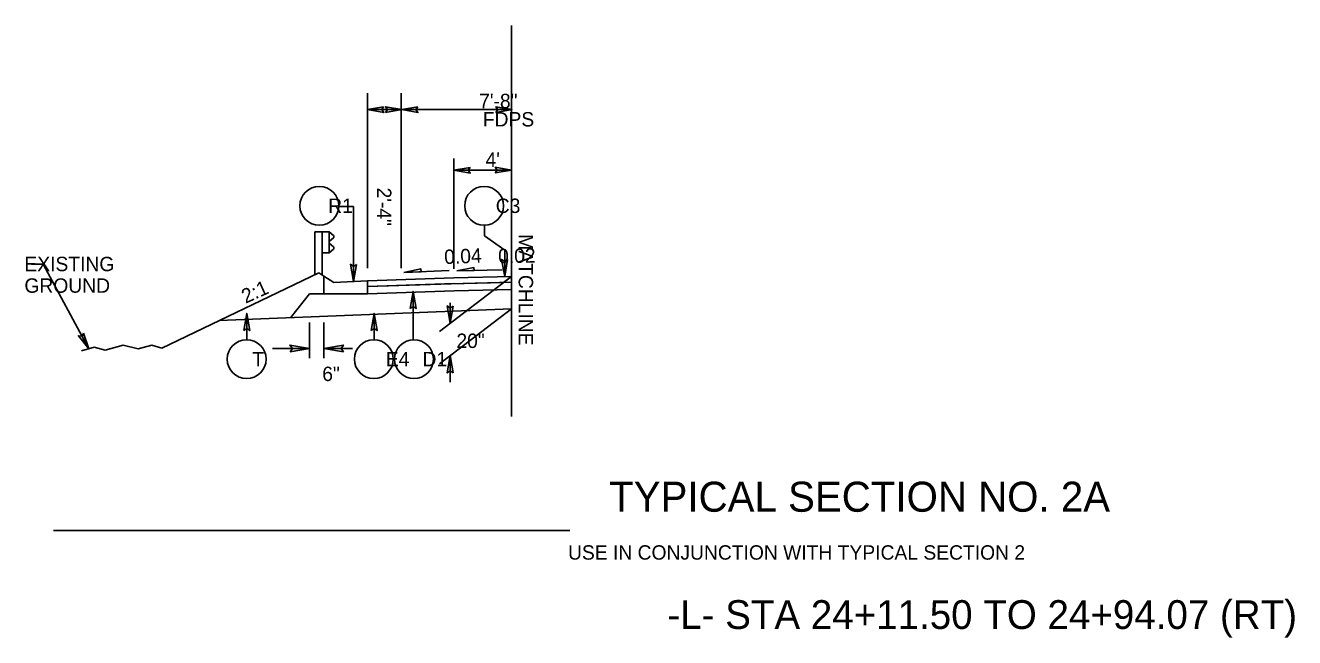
# Model space of a CAD drawing. Extents: x 574442 to 2463611, y -53527 to 675895.
# Drawn here: x 2463523.4 to 2463611.5, y 675852 to 675894.6 of the extents above; entities that cross this region are included whole.
import ezdxf

# ---------------------------------------------------------------- set-up
doc = ezdxf.new("R2010")
doc.units = 0
for name, color, linetype in [('Old_Level_1', 7, 'Continuous'), ('Old_Level_22', 7, 'Continuous'), ('Old_Level_23', 7, 'Continuous'), ('Old_Level_3', 7, 'Continuous'), ('Prop Shade Heavy', 7, 'Continuous'), ('Typical Curb CELL', 7, 'Continuous'), ('Typical Guardrail CELL', 7, 'Continuous')]:
    doc.layers.add(name, color=color, linetype=linetype)

msp = doc.modelspace()

# ---------------------------------------------------------------- linework, layer by layer
at = {"layer": 'Old_Level_1'}
msp.add_line((2463557.126, 675887.114), (2463557.126, 675887.114), dxfattribs=at)
at = {"layer": 'Old_Level_22'}
for p, q in [((2463543.749, 675877.391), (2463532.851, 675872.157)), ((2463544.106, 675877.148), (2463543.749, 675877.391)), ((2463553.126, 675877.03), (2463547.126, 675876.822)), ((2463557.126, 675877.134), (2463553.126, 675877.03)), ((2463553.14, 675876.63), (2463547.126, 675876.424)), ((2463553.157, 675876.131), (2463547.126, 675875.919)), ((2463557.126, 675876.732), (2463552.939, 675876.622)), ((2463557.126, 675876.231), (2463553.157, 675876.131)), ((2463543.106, 675875.919), (2463541.783, 675874.266)), ((2463543.106, 675875.919), (2463544.106, 675875.919)), ((2463557.126, 675874.879), (2463536.829, 675874.067))]:
    msp.add_line(p, q, dxfattribs=at)
msp.add_lwpolyline([(2463532.851, 675872.157), (2463532.152, 675872.348), (2463531.199, 675872.109), (2463530.165, 675872.348), (2463528.913, 675872.007), (2463528.151, 675872.211), (2463527.28, 675871.973)], dxfattribs=at)
at = {"layer": 'Old_Level_23'}
for p, q in [((2463557.126, 675894.569), (2463557.126, 675867.406)), ((2463547.126, 675889.867), (2463547.126, 675877.7)), ((2463549.459, 675889.867), (2463549.459, 675877.7)), ((2463557.169, 675888.716), (2463547.169, 675888.716)), ((2463553.126, 675885.325), (2463553.126, 675877.652)), ((2463557.126, 675884.51), (2463553.126, 675884.51)), ((2463545.137, 675881.992), (2463546.169, 675881.992)), ((2463546.169, 675876.78), (2463546.169, 675881.992)), ((2463555.244, 675879.952), (2463555.244, 675880.688)), ((2463556.653, 675878.949), (2463555.244, 675879.952)), ((2463556.653, 675877.123), (2463556.653, 675878.949)), ((2463524.626, 675877.973), (2463523.808, 675877.973)), ((2463527.779, 675872.11), (2463524.626, 675877.973)), ((2463552.795, 675877.537), (2463549.648, 675877.411)), ((2463557.126, 675877.134), (2463552.134, 675873.313)), ((2463556.473, 675877.585), (2463553.324, 675877.526)), ((2463550.289, 675876.091), (2463550.289, 675872.736)), ((2463552.879, 675873.883), (2463552.879, 675875.298)), ((2463538.748, 675874.564), (2463538.748, 675872.738)), ((2463547.587, 675874.564), (2463547.587, 675872.738)), ((2463557.126, 675874.879), (2463552.134, 675871.058)), ((2463543.106, 675873.935), (2463543.106, 675871.453)), ((2463544.106, 675873.935), (2463544.106, 675871.453)), ((2463543.106, 675872.123), (2463540.543, 675872.123)), ((2463544.106, 675872.123), (2463546.095, 675872.123)), ((2463552.879, 675869.776), (2463552.879, 675871.629))]:
    msp.add_line(p, q, dxfattribs=at)
for points in [[(2463548.251, 675888.909), (2463547.126, 675888.716), (2463548.257, 675888.516), (2463548.113, 675888.716)], [(2463548.378, 675888.522), (2463549.503, 675888.716), (2463548.371, 675888.916), (2463548.515, 675888.716)], [(2463550.628, 675888.909), (2463549.503, 675888.716), (2463550.634, 675888.516), (2463550.49, 675888.716)], [(2463556.044, 675888.522), (2463557.169, 675888.716), (2463556.038, 675888.916), (2463556.182, 675888.716)], [(2463554.251, 675884.703), (2463553.126, 675884.51), (2463554.257, 675884.31), (2463554.113, 675884.51)], [(2463556.001, 675884.316), (2463557.126, 675884.51), (2463555.995, 675884.71), (2463556.138, 675884.51)], [(2463546.374, 675877.968), (2463546.169, 675876.78), (2463545.958, 675877.974), (2463546.169, 675877.823)], [(2463553.324, 675877.526), (2463554.519, 675877.748), (2463554.523, 675877.548)], [(2463556.857, 675878.311), (2463556.653, 675877.123), (2463556.441, 675878.317), (2463556.653, 675878.166)], [(2463549.648, 675877.411), (2463550.838, 675877.659), (2463550.846, 675877.459)], [(2463550.084, 675874.902), (2463550.289, 675876.091), (2463550.5, 675874.896), (2463550.289, 675875.048)], [(2463538.543, 675873.376), (2463538.748, 675874.564), (2463538.959, 675873.369), (2463538.748, 675873.521)], [(2463547.382, 675873.376), (2463547.587, 675874.564), (2463547.798, 675873.369), (2463547.587, 675873.521)], [(2463553.084, 675875.072), (2463552.879, 675873.883), (2463552.668, 675875.078), (2463552.879, 675874.926)], [(2463527.417, 675873.192), (2463527.779, 675872.11), (2463527.067, 675873.011), (2463527.312, 675872.98)], [(2463541.756, 675871.891), (2463543.106, 675872.123), (2463541.748, 675872.363), (2463541.921, 675872.123)], [(2463545.456, 675871.891), (2463544.106, 675872.123), (2463545.463, 675872.363), (2463545.291, 675872.123)], [(2463553.084, 675870.44), (2463552.879, 675871.629), (2463552.668, 675870.434), (2463552.879, 675870.586)]]:
    msp.add_lwpolyline(points, close=True, dxfattribs=at)
for centre in [(2463543.788, 675882.038), (2463555.225, 675882.038), (2463538.74, 675871.388), (2463547.569, 675871.388), (2463550.353, 675871.388)]:
    msp.add_circle(centre, 1.35, dxfattribs=at)
at = {"layer": 'Old_Level_3'}
msp.add_line((2463561.185, 675859.48), (2463525.324, 675859.48), dxfattribs=at)
at = {"layer": 'Prop Shade Heavy'}
for p, q in [((2463553.126, 675877.03), (2463547.126, 675876.822)), ((2463557.126, 675877.134), (2463553.126, 675877.03)), ((2463557.126, 675877.134), (2463556.581, 675876.717)), ((2463556.581, 675876.717), (2463557.126, 675877.134)), ((2463557.126, 675876.732), (2463557.126, 675877.134)), ((2463547.126, 675876.822), (2463547.126, 675876.424)), ((2463547.126, 675876.424), (2463552.938, 675876.623)), ((2463552.939, 675876.622), (2463556.581, 675876.717)), ((2463556.581, 675876.717), (2463557.126, 675876.732))]:
    msp.add_line(p, q, dxfattribs=at)
msp.add_lwpolyline([(2463552.938, 675876.623), (2463552.939, 675876.622)], dxfattribs=at)
at = {"layer": 'Typical Curb CELL'}
for p, q in [((2463544.106, 675875.919), (2463544.106, 675877.148)), ((2463544.793, 675876.718), (2463544.106, 675877.148)), ((2463547.126, 675876.822), (2463544.793, 675876.718)), ((2463547.126, 675875.919), (2463547.126, 675876.822)), ((2463544.106, 675875.919), (2463547.126, 675875.919))]:
    msp.add_line(p, q, dxfattribs=at)
at = {"layer": 'Typical Guardrail CELL'}
for p, q in [((2463543.976, 675880.222), (2463543.479, 675880.222)), ((2463543.479, 675880.222), (2463543.479, 675877.261)), ((2463543.976, 675880.222), (2463543.976, 675877.236)), ((2463543.976, 675880.222), (2463544.474, 675880.222)), ((2463544.474, 675880.222), (2463544.474, 675878.772)), ((2463544.474, 675880.222), (2463544.763, 675879.968)), ((2463544.474, 675879.556), (2463544.763, 675879.809)), ((2463544.474, 675879.497), (2463544.474, 675879.556)), ((2463543.976, 675878.772), (2463544.474, 675878.772)), ((2463544.474, 675879.497), (2463544.474, 675879.439)), ((2463544.474, 675879.439), (2463544.763, 675879.185)), ((2463544.474, 675878.772), (2463544.763, 675879.026))]:
    msp.add_line(p, q, dxfattribs=at)
for centre, major_axis, start_param, end_param in [((2463544.719, 675879.889), (0, -0.0971), 0.61067, 2.530675), ((2463544.719, 675879.106), (0, 0.0971), 3.751819, 5.672217)]:
    msp.add_ellipse(centre, major_axis=major_axis, ratio=0.8, start_param=start_param, end_param=end_param, dxfattribs=at)

# ---------------------------------------------------------------- texts
at = {"layer": 'Old_Level_23'}
for s, p in [('7\'-8"', (2463554.878, 675888.815)), ('FDPS', (2463555.134, 675887.547)), ("4'", (2463555.321, 675884.743)), ('R1', (2463544.402, 675881.538)), ('C3', (2463556.032, 675881.538)), ('EXISTING', (2463523.314, 675877.497)), ('GROUND', (2463523.314, 675875.997)), ('20"', (2463553.302, 675872.161)), ('T', (2463539.133, 675870.888)), ('E4', (2463548.403, 675870.888)), ('D1', (2463550.952, 675870.888)), ('6"', (2463543.988, 675869.865)), (' USE IN CONJUNCTION WITH TYPICAL SECTION 2', (2463560.678, 675857.46))]:
    msp.add_text(s, height=1, dxfattribs=at).set_placement(p)
for s, rotation, p in [('2\'-4"', 270, (2463547.789, 675883.303)), ('MATCHLINE', 270, (2463557.622, 675880.061)), ('0.04 ', 2.29061, (2463552.473, 675877.987)), ('0.02', 1.08445, (2463556.204, 675878.042)), ('2:1', 24.17251, (2463538.662, 675875.229))]:
    msp.add_text(s, height=1, rotation=rotation, dxfattribs=at).set_placement(p)
at = {"layer": 'Old_Level_3'}
for s, height, p in [(' TYPICAL SECTION NO. 2A', 2.08913, (2463563.126, 675860.787)), ('-L- STA 24+11.50 TO 24+94.07 (RT)', 2, (2463567.948, 675852.646))]:
    msp.add_text(s, height=height, dxfattribs=at).set_placement(p)

doc.saveas('drawing.dxf')
